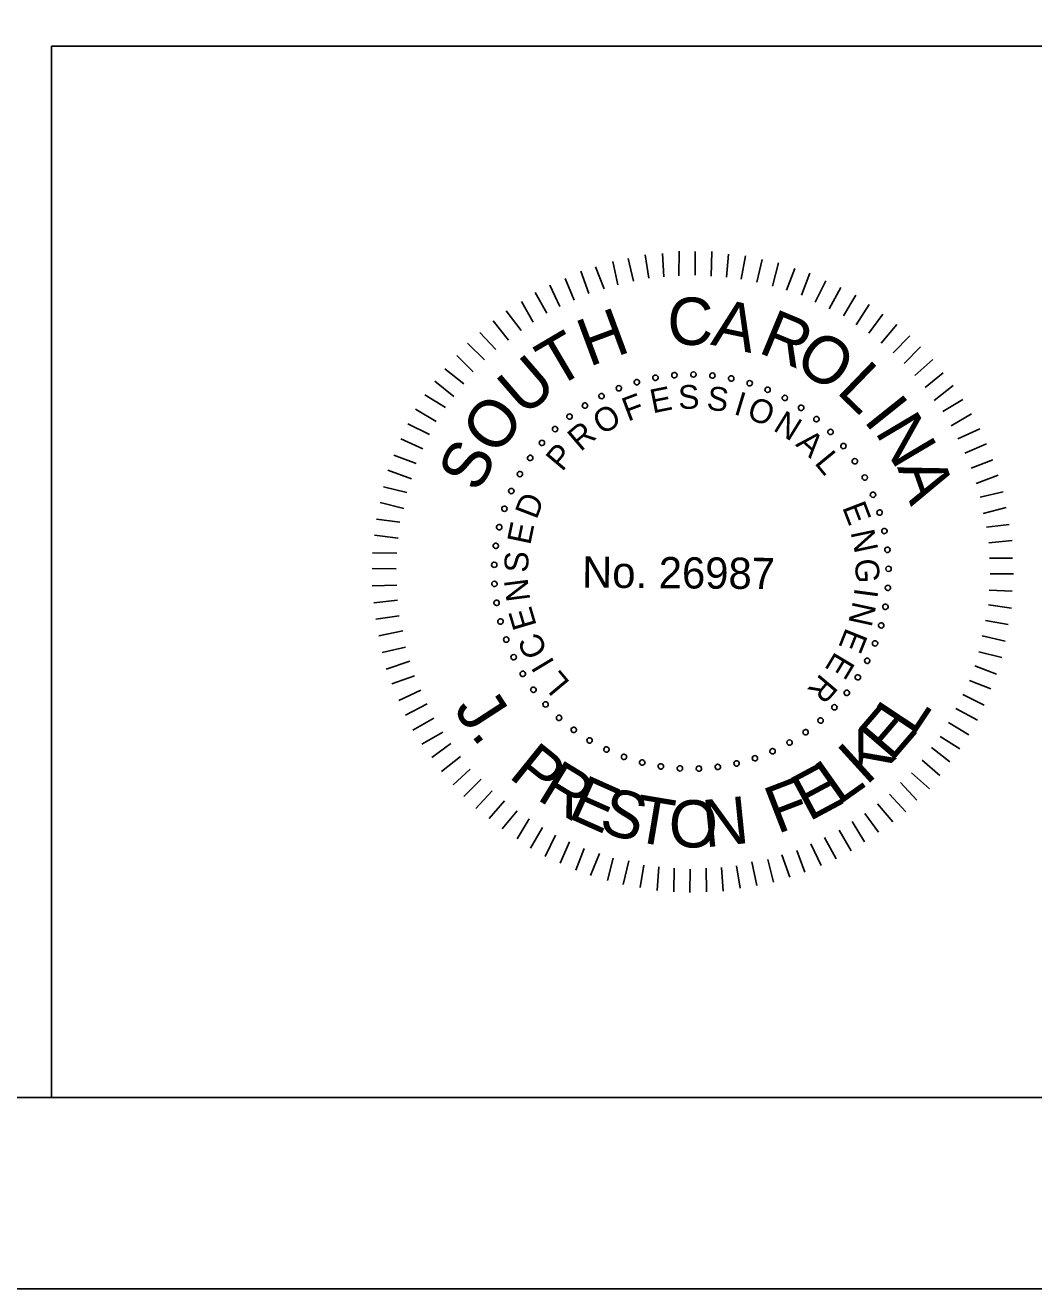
# Model space of a CAD drawing. Extents: x -125.5 to -89.4, y -5.1 to 16.9.
# Drawn here: x -102.967 to -100.331, y -5.066 to -1.761 of the extents above; entities that cross this region are included whole.
import ezdxf

# ---------------------------------------------------------------- set-up
doc = ezdxf.new("R2010")
doc.units = 0
for name, color, linetype in [('BR_BORDER LINES', 7, 'Continuous'), ('BR_TEXT', 7, 'Continuous'), ('Level 31', 7, 'Continuous')]:
    doc.layers.add(name, color=color, linetype=linetype)

msp = doc.modelspace()

# ---------------------------------------------------------------- linework, layer by layer
at = {"layer": 'BR_BORDER LINES'}
for p, q in [((-102.8989, -1.8161), (-97.5337, -1.8161)), ((-102.8989, -4.5661), (-102.8989, -1.8161)), ((-123.6994, -4.5662), (-90.0334, -4.5662))]:
    msp.add_line(p, q, dxfattribs=at)
at = {"layer": 'BR_TEXT'}
for p, q in [((-101.418, -2.4404), (-101.4312, -2.3793)), ((-101.3767, -2.4304), (-101.3908, -2.3711)), ((-101.3372, -2.423), (-101.3461, -2.362)), ((-101.2977, -2.419), (-101.3015, -2.3581)), ((-101.2582, -2.4168), (-101.2576, -2.3524)), ((-101.2161, -2.4146), (-101.2156, -2.3528)), ((-101.1741, -2.4175), (-101.1718, -2.3531)), ((-101.1338, -2.4204), (-101.129, -2.3595)), ((-101.0952, -2.425), (-101.0844, -2.3642)), ((-101.0549, -2.4331), (-101.0407, -2.374)), ((-101.4937, -2.4629), (-101.5147, -2.4044)), ((-101.4541, -2.4504), (-101.476, -2.3927)), ((-101.0138, -2.4437), (-100.9979, -2.3829)), ((-100.977, -2.4543), (-100.9551, -2.397)), ((-100.9376, -2.4675), (-100.9157, -2.4093)), ((-101.5695, -2.4966), (-101.5957, -2.4406)), ((-101.5325, -2.4798), (-101.556, -2.4238)), ((-100.9017, -2.485), (-100.8738, -2.4294)), ((-101.604, -2.5144), (-101.6344, -2.46)), ((-100.8658, -2.5024), (-100.8345, -2.4469)), ((-100.8282, -2.5208), (-100.796, -2.467)), ((-101.6704, -2.5593), (-101.7095, -2.5083)), ((-101.6394, -2.5381), (-101.6698, -2.4838)), ((-100.795, -2.5451), (-100.761, -2.4913)), ((-101.7041, -2.5847), (-101.744, -2.5346)), ((-100.7617, -2.5668), (-100.7252, -2.5165)), ((-100.7293, -2.5928), (-100.6886, -2.5434)), ((-101.7369, -2.6094), (-101.7786, -2.5644)), ((-100.6977, -2.618), (-100.6545, -2.5737)), ((-101.7663, -2.6366), (-101.8106, -2.5925)), ((-100.6697, -2.6456), (-100.6264, -2.6022)), ((-101.7958, -2.6673), (-101.8392, -2.6248)), ((-100.6416, -2.6768), (-100.594, -2.6351)), ((-101.8209, -2.6988), (-101.8704, -2.6598)), ((-100.6144, -2.7088), (-100.5677, -2.6705)), ((-101.8469, -2.732), (-101.8964, -2.6922)), ((-100.5906, -2.7424), (-100.5414, -2.7033)), ((-101.8686, -2.761), (-101.9224, -2.728)), ((-100.5686, -2.7718), (-100.516, -2.7396)), ((-101.893, -2.7977), (-101.9467, -2.7656)), ((-101.9104, -2.8319), (-101.9668, -2.804)), ((-100.5466, -2.8089), (-100.4931, -2.7776)), ((-100.5288, -2.8433), (-100.4711, -2.8164)), ((-101.9279, -2.8687), (-101.9852, -2.8433)), ((-100.5111, -2.8804), (-100.4543, -2.856)), ((-101.9454, -2.9072), (-102.0035, -2.8852)), ((-100.4943, -2.9192), (-100.4374, -2.8982)), ((-101.9577, -2.9474), (-102.0193, -2.9246)), ((-100.4809, -2.9596), (-100.4232, -2.9378)), ((-101.97, -2.9833), (-102.0308, -2.9682)), ((-100.4708, -2.9957), (-100.4107, -2.9816)), ((-101.9772, -3.0253), (-102.0397, -3.0094)), ((-100.4626, -3.0378), (-100.4024, -3.0229)), ((-101.9878, -3.0613), (-102.0487, -3.0531)), ((-100.4543, -3.074), (-100.3951, -3.0667)), ((-101.9925, -3.1024), (-102.0542, -3.0951)), ((-100.4478, -3.1152), (-100.3868, -3.1088)), ((-101.9954, -3.1419), (-102.0597, -3.1414)), ((-100.4464, -3.1547), (-100.3863, -3.1552)), ((-101.9974, -3.183), (-102.06, -3.1825)), ((-100.4442, -3.1959), (-100.3833, -3.1964)), ((-101.9961, -3.226), (-102.0604, -3.2272)), ((-100.4471, -3.2388), (-100.3871, -3.241)), ((-101.9938, -3.2646), (-102.0556, -3.2718)), ((-100.4492, -3.2774), (-100.3883, -3.2856)), ((-101.9898, -3.3058), (-102.0509, -3.3148)), ((-100.4564, -3.3185), (-100.3972, -3.3284)), ((-101.9799, -3.3454), (-102.0426, -3.3586)), ((-100.4653, -3.3579), (-100.4053, -3.3721)), ((-101.9733, -3.3875), (-102.0344, -3.4016)), ((-100.4742, -3.3999), (-100.4143, -3.415)), ((-101.9616, -3.4245), (-102.0236, -3.4454)), ((-100.4848, -3.4367), (-100.4275, -3.4586)), ((-101.95, -3.4632), (-102.0085, -3.4842)), ((-101.9331, -3.5003), (-101.9908, -3.5272)), ((-100.4989, -3.4752), (-100.4424, -3.4971)), ((-100.5163, -3.512), (-100.4599, -3.5399)), ((-101.9162, -3.5364), (-101.9731, -3.566)), ((-100.5346, -3.5479), (-100.4774, -3.5784)), ((-101.8994, -3.5735), (-101.9537, -3.6048)), ((-100.553, -3.5846), (-100.5, -3.6168)), ((-101.8756, -3.6106), (-101.93, -3.6419)), ((-100.5756, -3.6213), (-100.5235, -3.6535)), ((-101.8544, -3.6399), (-101.9045, -3.6764)), ((-100.5981, -3.6503), (-100.5495, -3.6876)), ((-101.829, -3.6736), (-101.8791, -3.7127)), ((-100.6224, -3.6836), (-100.5764, -3.7234)), ((-101.8043, -3.7073), (-101.8485, -3.7481)), ((-101.7754, -3.7333), (-101.8204, -3.7784)), ((-100.6502, -3.7168), (-100.6033, -3.7584)), ((-101.7465, -3.7636), (-101.7889, -3.8095)), ((-100.6787, -3.7423), (-100.6362, -3.7882)), ((-101.714, -3.7895), (-101.7548, -3.8364)), ((-100.7392, -3.7976), (-100.6993, -3.8452)), ((-100.7073, -3.7721), (-100.6648, -3.8188)), ((-101.6808, -3.8156), (-101.7207, -3.8633)), ((-100.772, -3.8231), (-100.7364, -3.8714)), ((-101.6501, -3.8373), (-101.6814, -3.8894)), ((-101.6151, -3.8599), (-101.6464, -3.9137)), ((-100.8393, -3.8663), (-100.808, -3.9206)), ((-100.8057, -3.8443), (-100.7727, -3.8969)), ((-101.5809, -3.8799), (-101.608, -3.9355)), ((-101.5442, -3.8974), (-101.5687, -3.953)), ((-100.8773, -3.8857), (-100.8468, -3.9418)), ((-101.5057, -3.9149), (-101.5276, -3.9713)), ((-101.4663, -3.9272), (-101.4891, -3.9854)), ((-100.9892, -3.9311), (-100.9682, -3.9897)), ((-100.9496, -3.9194), (-100.9286, -3.9763)), ((-100.9135, -3.9026), (-100.8865, -3.9586)), ((-101.4304, -3.9395), (-101.4446, -3.9986)), ((-101.3892, -3.9467), (-101.4044, -4.0084)), ((-101.3499, -3.9582), (-101.3598, -4.0165)), ((-101.3104, -3.9628), (-101.3152, -4.0246)), ((-101.271, -3.9657), (-101.2715, -4.0275)), ((-101.1466, -3.9642), (-101.1428, -4.026)), ((-101.1079, -3.9602), (-101.098, -4.0186)), ((-101.0675, -3.9494), (-101.0542, -4.0113)), ((-101.0262, -3.9429), (-101.0112, -4.0022)), ((-101.229, -3.9686), (-101.2295, -4.0296)), ((-101.1869, -3.9664), (-101.1857, -4.0282))]:
    msp.add_line(p, q, dxfattribs=at)
for centre, start, end in [((-101.3196, -2.6831), 10.6038, 190.6038), ((-101.2702, -2.6764), 5.0653, 185.0653), ((-101.2702, -2.6764), 185.0653, 5.0653), ((-101.2204, -2.6745), 359.5268, 179.5268), ((-101.2204, -2.6745), 179.5268, 359.5268), ((-101.1707, -2.6774), 173.9884, 353.9884), ((-101.1707, -2.6774), 353.9884, 173.9884), ((-101.4153, -2.7106), 21.6807, 201.6807), ((-101.4153, -2.7106), 201.6807, 21.6807), ((-101.3681, -2.6945), 16.1422, 196.1422), ((-101.3681, -2.6945), 196.1422, 16.1422), ((-101.3196, -2.6831), 190.6038, 10.6038), ((-101.1214, -2.6851), 168.4499, 348.4499), ((-101.1214, -2.6851), 348.4499, 168.4499), ((-101.0732, -2.6976), 162.9114, 342.9114), ((-101.0732, -2.6976), 342.9114, 162.9114), ((-101.0263, -2.7146), 337.373, 157.373), ((-101.4607, -2.7311), 27.2191, 207.2191), ((-101.4607, -2.7311), 207.2191, 27.2191), ((-101.0263, -2.7146), 157.373, 337.373), ((-100.9814, -2.736), 151.8345, 331.8345), ((-100.9814, -2.736), 331.8345, 151.8345), ((-101.5039, -2.7559), 32.7576, 212.7576), ((-101.5039, -2.7559), 212.7576, 32.7576), ((-100.9387, -2.7617), 146.2961, 326.2961), ((-100.9387, -2.7617), 326.2961, 146.2961), ((-101.5445, -2.7848), 38.2961, 218.2961), ((-101.5445, -2.7848), 218.2961, 38.2961), ((-100.8987, -2.7914), 140.7576, 320.7576), ((-100.8987, -2.7914), 320.7576, 140.7576), ((-101.5821, -2.8175), 43.8345, 223.8345), ((-101.5821, -2.8175), 223.8345, 43.8345), ((-100.8617, -2.8249), 135.2191, 315.2191), ((-100.8617, -2.8249), 315.2191, 135.2191), ((-101.6164, -2.8536), 49.373, 229.373), ((-101.6164, -2.8536), 229.373, 49.373), ((-100.8282, -2.8617), 129.6807, 309.6807), ((-100.8282, -2.8617), 309.6807, 129.6807), ((-101.6471, -2.8929), 54.9114, 234.9114), ((-101.6471, -2.8929), 234.9114, 54.9114), ((-100.7983, -2.9016), 124.1422, 304.1422), ((-100.7983, -2.9016), 304.1422, 124.1422), ((-101.6738, -2.935), 60.4499, 240.4499), ((-101.6738, -2.935), 240.4499, 60.4499), ((-100.7724, -2.9442), 118.6038, 298.6038), ((-100.7724, -2.9442), 298.6038, 118.6038), ((-101.6964, -2.9794), 65.9884, 245.9884), ((-101.6964, -2.9794), 245.9884, 65.9884), ((-100.7508, -2.9891), 113.0653, 293.0653), ((-100.7508, -2.9891), 293.0653, 113.0653), ((-101.7145, -3.0258), 71.5268, 251.5268), ((-101.7145, -3.0258), 251.5268, 71.5268), ((-100.7336, -3.0359), 107.5268, 287.5268), ((-100.7336, -3.0359), 287.5268, 107.5268), ((-101.7281, -3.0738), 77.0653, 257.0653), ((-101.7281, -3.0738), 257.0653, 77.0653), ((-100.721, -3.0841), 101.9884, 281.9884), ((-100.721, -3.0841), 281.9884, 101.9884), ((-101.737, -3.1228), 82.6038, 262.6038), ((-101.737, -3.1228), 262.6038, 82.6038), ((-100.7131, -3.1333), 96.4499, 276.4499), ((-100.7131, -3.1333), 276.4499, 96.4499), ((-101.7411, -3.1724), 88.1422, 268.1422), ((-101.7411, -3.1724), 268.1422, 88.1422), ((-100.71, -3.183), 90.9114, 270.9114), ((-100.71, -3.183), 270.9114, 90.9114), ((-101.7404, -3.2223), 93.6807, 273.6807), ((-101.7404, -3.2223), 273.6807, 93.6807), ((-100.7118, -3.2328), 85.373, 265.373), ((-100.7118, -3.2328), 265.373, 85.373), ((-101.7349, -3.2718), 99.2191, 279.2191), ((-101.7349, -3.2718), 279.2191, 99.2191), ((-100.7183, -3.2822), 79.8345, 259.8345), ((-100.7183, -3.2822), 259.8345, 79.8345), ((-101.7246, -3.3206), 104.7576, 284.7576), ((-101.7246, -3.3206), 284.7576, 104.7576), ((-100.7295, -3.3308), 74.2961, 254.2961), ((-100.7295, -3.3308), 254.2961, 74.2961), ((-101.7097, -3.3681), 110.2961, 290.2961), ((-101.7097, -3.3681), 290.2961, 110.2961), ((-100.7454, -3.378), 68.7576, 248.7576), ((-100.7454, -3.378), 248.7576, 68.7576), ((-101.6903, -3.414), 115.8345, 295.8345), ((-101.6903, -3.414), 295.8345, 115.8345), ((-100.7658, -3.4235), 63.2191, 243.2191), ((-100.7658, -3.4235), 243.2191, 63.2191), ((-101.6665, -3.4578), 121.373, 301.373), ((-101.6665, -3.4578), 301.373, 121.373), ((-100.7904, -3.4668), 57.6807, 237.6807), ((-100.7904, -3.4668), 237.6807, 57.6807), ((-101.6386, -3.4991), 126.9114, 306.9114), ((-101.6386, -3.4991), 306.9114, 126.9114), ((-100.8192, -3.5075), 52.1422, 232.1422), ((-100.8192, -3.5075), 232.1422, 52.1422), ((-101.6069, -3.5375), 132.4499, 312.4499), ((-101.6069, -3.5375), 312.4499, 132.4499), ((-101.5716, -3.5727), 137.9884, 317.9884), ((-101.5716, -3.5727), 317.9884, 137.9884), ((-100.8517, -3.5452), 46.6038, 226.6038), ((-100.8517, -3.5452), 226.6038, 46.6038), ((-101.5331, -3.6043), 143.5268, 323.5268), ((-101.5331, -3.6043), 323.5268, 143.5268), ((-100.8877, -3.5797), 41.0653, 221.0653), ((-100.8877, -3.5797), 221.0653, 41.0653), ((-101.4917, -3.632), 149.0653, 329.0653), ((-101.4917, -3.632), 329.0653, 149.0653), ((-100.9688, -3.6374), 29.9884, 209.9884), ((-100.9688, -3.6374), 209.9884, 29.9884), ((-100.9269, -3.6105), 35.5268, 215.5268), ((-100.9269, -3.6105), 215.5268, 35.5268), ((-101.4478, -3.6556), 154.6038, 334.6038), ((-101.4478, -3.6556), 334.6038, 154.6038), ((-101.4018, -3.6749), 340.1422, 160.1422), ((-101.0132, -3.6601), 24.4499, 204.4499), ((-101.0132, -3.6601), 204.4499, 24.4499), ((-101.4018, -3.6749), 160.1422, 340.1422), ((-101.3542, -3.6896), 165.6807, 345.6807), ((-101.3542, -3.6896), 345.6807, 165.6807), ((-101.3054, -3.6997), 351.2191, 171.2191), ((-101.3054, -3.6997), 171.2191, 351.2191), ((-101.2559, -3.705), 356.7576, 176.7576), ((-101.2061, -3.7055), 2.2961, 182.2961), ((-101.1564, -3.7012), 7.8345, 187.8345), ((-101.1564, -3.7012), 187.8345, 7.8345), ((-101.1074, -3.6921), 13.373, 193.373), ((-101.1074, -3.6921), 193.373, 13.373), ((-101.0595, -3.6784), 18.9114, 198.9114), ((-101.0595, -3.6784), 198.9114, 18.9114), ((-101.2559, -3.705), 176.7576, 356.7576), ((-101.2061, -3.7055), 182.2961, 2.2961)]:
    msp.add_arc(centre, 0.00701, start, end, dxfattribs=at)
at = {"layer": 'Level 31'}
msp.add_lwpolyline([(-125.5328, 16.9339), (-125.5328, -5.0661), (-89.5328, -5.0661), (-89.5328, 16.9339)], dxfattribs=at)

# ---------------------------------------------------------------- texts
at = {"layer": 'BR_TEXT'}
for s, height, rotation, p in [('C', 0.1241, 359.5482, (-101.2889, -2.5969)), ('H', 0.1241, 20.3637, (-101.4933, -2.6552)), ('A', 0.1241, 348.1981, (-101.1775, -2.5961)), ('R', 0.1241, 337.4344, (-101.0542, -2.616)), ('T', 0.1241, 30.4992, (-101.5812, -2.7128)), ('O', 0.1239, 326.5869, (-100.962, -2.6528)), ('U', 0.1241, 40.8022, (-101.6624, -2.7875)), ('L', 0.1241, 315.9488, (-100.8494, -2.7205)), ('E', 0.0622, 11.4103, (-101.3269, -2.7764)), ('S', 0.0622, 2.208, (-101.2591, -2.7654)), ('S', 0.0622, 352.6608, (-101.1878, -2.7657)), ('O', 0.1241, 52.0267, (-101.7369, -2.8914)), ('F', 0.0622, 20.6127, (-101.392, -2.7981)), ('I', 0.0622, 343.1136, (-101.1175, -2.7777)), ('O', 0.0622, 338.4392, (-101.0841, -2.7878)), ('I', 0.1241, 308.6613, (-100.778, -2.7948)), ('O', 0.0622, 30.8477, (-101.4594, -2.8341)), ('N', 0.0622, 328.2042, (-101.0145, -2.8192)), ('N', 0.1241, 300.7037, (-100.7474, -2.8242)), ('R', 0.0622, 40.3949, (-101.5156, -2.878)), ('A', 0.0622, 318.657, (-100.9555, -2.8592)), ('S', 0.1239, 63.2511, (-101.7823, -2.9871)), ('P', 0.0622, 49.9421, (-101.5636, -2.9306)), ('L', 0.0622, 309.4546, (-100.9057, -2.9066)), ('A', 0.1241, 289.4792, (-100.6882, -2.9172)), ('D', 0.0622, 69.0364, (-101.6306, -3.0559)), ('E', 0.0622, 291.049, (-100.8319, -3.0219)), ('E', 0.0622, 78.2388, (-101.6472, -3.1226)), ('N', 0.0622, 281.8466, (-100.8097, -3.0869)), ('S', 0.0622, 87.786, (-101.6529, -3.1936)), ('No. 26987', 0.08175, 359.5268, (-101.5118, -3.232)), ('G', 0.0622, 272.2995, (-100.7979, -3.1572)), ('N', 0.0622, 97.3332, (-101.6467, -3.2646)), ('I', 0.0622, 262.4084, (-100.7983, -3.231)), ('E', 0.0622, 106.5355, (-101.6297, -3.3312)), ('N', 0.0622, 257.7339, (-100.8028, -3.2656)), ('C', 0.0622, 116.4266, (-101.5998, -3.3987)), ('E', 0.0622, 248.1867, (-100.8209, -3.3346)), ('E', 0.0622, 238.9844, (-100.8488, -3.3973)), ('I', 0.0622, 121.1011, (-101.5818, -3.4285)), ('L', 0.0622, 129.9595, (-101.5411, -3.4807)), ('R', 0.0622, 229.782, (-100.8865, -3.4548)), ('J', 0.1236, 302.9559, (-101.849, -3.5492)), ('E', 0.1236, 49.3639, (-100.703, -3.6911)), ('L', 0.1236, 56.4247, (-100.6455, -3.6233)), ('K', 0.1236, 42.3031, (-100.7683, -3.7512)), ('.', 0.1236, 309.3974, (-101.8049, -3.6172)), ('P', 0.1236, 321.1035, (-101.7065, -3.7264)), ('R', 0.1236, 328.5359, (-101.6332, -3.7844)), ('E', 0.1236, 28.1814, (-100.9186, -3.8452)), ('L', 0.1236, 35.2422, (-100.8406, -3.8028)), ('E', 0.1236, 335.9684, (-101.5531, -3.8325)), ('F', 0.1236, 21.1206, (-101.0013, -3.8776)), ('S', 0.1236, 343.0292, (-101.4718, -3.8682)), ('T', 0.1236, 350.4617, (-101.3821, -3.8947)), ('O', 0.1236, 358.1419, (-101.2867, -3.9097)), ('N', 0.1236, 5.8221, (-101.1902, -3.9118))]:
    msp.add_text(s, height=height, rotation=rotation, dxfattribs=at).set_placement(p)

doc.saveas('drawing.dxf')
